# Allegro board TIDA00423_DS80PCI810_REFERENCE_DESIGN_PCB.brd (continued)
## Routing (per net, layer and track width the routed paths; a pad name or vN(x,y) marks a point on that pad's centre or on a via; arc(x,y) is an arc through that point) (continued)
VDD_SEL3_4: length 5
  TOP w0.762: SW7.3 v1(82.39,35.2)
  BOTTOM w0.229: U4.25 v1(120.33,38.77) ; v1(75.52,38.75) 75.51,38.75 75.49,38.77 U3.25
VIN1_2: length 56.1
  TOP w0.229: U2.24 v1(119.88,25.03) ; U1.24 75.8,25.03
  TOP w0.292: 75.8,25.03 76.01,25.03
  TOP w0.508: 98.11,24.79 J3.2 ; C160.2 95.62,24.79 ; 76.01,25.03 77.03,25.03
  TOP w0.762: 77.03,25.03 80.09,25.03 81.27,26.21 91.35,26.21 92.8,24.76 C160.2 ; 95.62,24.79 98.11,24.79
  POWER1 w0.762: v1(107.83,19.19) 105.53,19.19 v1(100.7,24.03)
  BOTTOM w0.381: 100.7,24.88 C21.2
  BOTTOM w0.508: J3.2 98.27,24.95 ; v1(119.88,25.03) 119.56,25.03 119.06,24.53 119.06,24.41
  BOTTOM w0.762: v1(100.7,24.03) 100.7,24.88 ; 119.06,24.41 118.94,24.29 118.94,21.17 118.7,20.94 118.7,20.94 116.56,18.79 116.55,18.79 116.4,18.64 108.39,18.64 v1(107.83,19.19) ; 98.27,24.95 C21.2
VIN3_4: length 125.2
  POWER1 w0.229: 119.37,37.74 119.37,38.87 v1(119.77,39.27) ; 75.79,39.23 75.73,39.23 75.72,39.24 75,39.24 v1(74.97,39.27)
  POWER1 w0.292: 119.37,37.74 119.37,37.33 119.82,36.88 ; 119.85,26.86 119.32,26.33 119.32,22.02 ; 75.79,39.23 76.52,39.23 76.8,38.96
  POWER1 w0.508: 76.8,38.96 77.47,38.29 ; 119.8,21.05 119.32,21.54 119.32,22.02
  POWER1 w0.762: 119.82,36.88 120.27,36.43 120.27,27.29 119.85,26.86 ; 77.47,38.29 78.68,37.07 78.68,17.52 84.95,11.25 111.71,11.25 119.8,19.34 119.8,21.05
  BOTTOM w0.229: U4.24 v1(119.77,39.27) ; U3.24 v1(74.97,39.27) 75.85,39.27
  BOTTOM w0.292: 76.04,39.27 75.85,39.27
  BOTTOM w0.635: 77.53,39.27 76.04,39.27
  BOTTOM w0.762: C22.2 98.45,40.96 J5.2 98.36,38.94 C161.2 98.33,37.84 97.19,36.7 82.09,36.7 79.51,39.27 77.53,39.27
3_3V: length 30.2
  TOP w0.508: 84.39,20.6 85.54,20.6 85.86,20.28 85.86,20.27 v1(85.85,20.27) ; U6.4 v1(82.46,39.52)
  TOP w0.635: J1.B8 52.65,6.97 51.83,7.79 v1(51.8,7.79) ; J2.B8 52.65,58.12 v1(52.38,57.86)
  BOTTOM w0.381: J1.A9 53.65,7.59 v1(53.99,7.93)
  BOTTOM w0.508: v1(54.18,7.18) 54.65,6.71 J1.A10 ; v1(85.85,20.27) 85.41,20.71 C23.2 ; C24.2 83.9,39.52 v1(82.46,39.52)
  BOTTOM w0.635: v1(54.18,7.18) 54.18,7.73 v1(53.99,7.93) ; J2.A9 53.65,57.85 v1(53.94,57.56) 54.39,57.56 v1(54.65,57.82) J2.A10 ; R6.1 v1(87.33,43.71) ; R3.1 v1(87.48,24.79)
3_3VAUX: length 59.2
  TOP w0.292: J2.B10 54.65,58.7 55.31,58.04 55.31,56.92 52.46,54.07 52.46,10.99 54.85,8.61 54.85,6.46 54.65,6.26 J1.B10
A_D1: length 100.4
  TOP w0.229: U1.27 v1(75.53,26.53)
  TOP w0.292: R7.2 v1(131.12,30.03) ; SW9.8 v1(138.39,19.83)
  POWER1 w0.292: v1(138.39,19.83) 138.39,26.29 136.84,27.84 134.43,27.84 132.24,30.03 v1(131.12,30.03) 129.61,30.03 126.56,26.97 126.56,21.36 113.68,8.48 84.25,8.48 76.24,16.48 76.24,25.82 v1(75.53,26.53)
A_D2: length 32.3
  TOP w0.229: U2.27 120.89,26.53
  TOP w0.292: 120.89,26.53 127.06,26.53 128.24,27.71 130.75,27.71 132.86,29.82 132.86,30.76 ; 132.86,30.76 R8.2 ; 132.86,30.76 134.05,30.76 134.85,29.96 134.85,22.66 135.79,21.72 138.09,21.72 138.75,22.37 SW9.7
A_D3: length 121.5
  TOP w0.292: SW9.6 139.59,24.91 137.8,26.71 137.8,37.35 137.02,38.13 135.03,38.13 134.05,39.11 R9.2 v1(133.28,39.89)
  POWER1 w0.292: v1(133.28,39.89) 131.95,39.89 125.49,33.42 125.49,21.9 113.13,9.54 84.58,9.54 77.31,16.82 77.31,27.38 75.52,29.16 v1(75.52,37.75)
  BOTTOM w0.229: U3.27 75.5,37.77 v1(75.52,37.75)
A_D4: length 35
  TOP w0.292: v1(137.69,40.01) R10.2 136.97,39.14 138.32,37.79 138.32,30.55 140.29,28.58 SW9.5
  BOTTOM w0.229: U4.27 120.87,37.77
  BOTTOM w0.292: 120.87,37.77 126.33,37.77 129.07,40.51 137.19,40.51 v1(137.69,40.01)
DEMA0_SDA_DS: length 174.8
  TOP w0.229: 62.14,25.02 62.96,25.02 v1(62.98,25.03) U1.49 ; U2.49 v1(107.78,25.03)
  TOP w0.292: 49.85,50.86 49.85,50.26 48.32,48.74 41.21,48.74 39.81,50.14 39.81,50.26 ; 62.14,25.02 60.53,25.02 54.75,30.8 v1(54.75,32.08) ; 39.81,50.26 38.29,48.74 33.08,48.74 32.28,49.54 SW17.4 v1(32.28,52.42) ; 39.81,50.26 SW15.4
  POWER1 w0.229: v1(107.78,25.03) 107.85,25.1 108.21,25.1 109.52,26.41 109.52,26.87 ; 62.14,24.97 62.91,24.97 v1(62.98,25.03) ; 61.51,38.2 61.69,38.38 65.08,38.38 66.36,39.66 66.36,41.79 66.42,41.86 66.42,42.06 ; 106.48,38.27 106.5,38.29 108.61,38.29 109.16,37.74
  POWER1 w0.292: 109.16,37.74 109.52,37.38 109.52,26.87 ; 106.48,38.27 106.14,38.27 103.35,41.05 103.35,44.59 98.24,49.71 73.47,49.71 66.42,42.66 66.42,42.06 ; v1(54.75,32.08) 55.28,32.61 55.28,34.41 50.03,39.67 34.84,39.67 29.2,45.31 29.2,52.8 29.83,53.44 31.56,53.44 32.32,52.68 32.32,52.46 v1(32.28,52.42) ; 61.51,38.2 59.08,35.77 59.08,26.94 61.06,24.97 62.14,24.97
DEMA0_SDA_US: length 95.8
  TOP w0.292: SW16.4 36,38.45 37.02,39.47 38.54,39.47 39.81,40.74 SW15.1 39.81,43.76 39.89,43.84 v1(39.89,43.91)
  POWER1 w0.229: 65.43,42.06 65.43,40.9 63.87,39.34 61.77,39.34 v1(61.74,39.37) ; 106.48,39.33 106.53,39.28 v1(108.14,39.28)
  POWER1 w0.292: 65.43,42.06 65.43,43.65 72.48,50.7 98.69,50.7 104.53,44.85 104.53,41.27 106.48,39.33
  BOTTOM w0.229: v1(108.14,39.28) 108.14,39.28 108.15,39.27 U4.49 ; v1(61.74,39.37) 61.84,39.27 U3.49
  BOTTOM w0.292: v1(61.74,39.37) 44.42,39.37 v1(39.89,43.91)
DEMA1_SCL_DS: length 173.9
  TOP w0.229: U1.50 62.72,24.53 v1(62.49,24.31) 62.14,24.31 ; U2.50 v1(107.33,24.53)
  TOP w0.292: 62.14,24.31 60.54,24.31 54.22,30.63 54.22,32.71 v1(54.72,33.22) ; SW4.2 47.26,50.91 SW15.3 42.35,51.53 40.96,52.93 35.33,52.93 v1(34.82,52.42) SW17.3
  POWER1 w0.229: 110.01,26.87 110.01,26.3 108.25,24.53 v1(107.33,24.53) ; 109.86,37.74 108.83,38.77 106.62,38.77 ; 62.36,38.85 64.03,38.85 65.93,40.74 65.93,42.06
  POWER1 w0.292: v1(62.49,24.31) 61.02,24.31 58.59,26.74 58.59,36.24 61.19,38.85 62.36,38.85 ; 110.01,26.87 110.01,37.59 109.86,37.74 ; 65.93,42.06 65.93,43.08 73.05,50.2 98.44,50.2 103.9,44.75 103.9,41.21 106.33,38.77 106.62,38.77 ; v1(54.72,33.22) 49.19,38.76 34.4,38.76 28.68,44.49 28.68,53.04 29.59,53.95 33.31,53.95 34.82,52.44 v1(34.82,52.42)
DEMA1_SCL_US: length 92.7
  TOP w0.292: v1(42.35,43.91) SW15.2 42.35,40.36 41.08,39.09 39.31,39.09 38.54,38.33 SW16.3
  POWER1 w0.229: v1(62.47,39.88) 62.57,39.77 63.67,39.77 64.94,41.04 64.94,42.06 ; 106.48,40.19 106.9,39.77 v1(107.33,39.77)
  POWER1 w0.292: 106.48,40.19 105.12,41.55 105.12,45.08 98.95,51.25 72.23,51.25 64.94,43.96 64.94,42.06
  BOTTOM w0.229: 62.15,39.9 62.18,39.88 v1(62.47,39.88) 62.57,39.77 U3.50 ; U4.50 v1(107.33,39.77)
  BOTTOM w0.292: 62.15,39.9 46.36,39.9 v1(42.35,43.91)
DEMB0_AD1_DS: length 184.9
  TOP w0.229: U1.53 v1(62.98,23.03) ; U2.53 v1(107.78,23.03)
  TOP w0.292: SW17.1 v1(32.28,44) ; 17.84,26.55 SW5.11 22.92,26.55 v1(22.92,28.29)
  POWER1 w0.229: 62.14,23.04 62.97,23.04 v1(62.98,23.03) 62.98,23.03 63.43,22.58 63.43,22.22 ; 106.48,41.83 106.95,41.36 108.36,41.36 109.61,40.11 109.61,39.39 111.02,37.98 111.02,37.74 ; 61.07,40.99 62.68,40.99 63.75,42.06 ; 110.3,23.04 107.79,23.04 v1(107.78,23.03)
  POWER1 w0.292: 63.43,22.22 63.43,21.78 62.68,21.03 54.95,21.03 48.35,27.63 23.58,27.63 v1(22.92,28.29) ; 63.75,42.06 63.87,42.18 63.87,44.57 71.58,52.28 99.48,52.28 106.31,45.45 106.31,42 106.48,41.83 ; 111.02,37.74 111.02,23.76 110.3,23.04 ; 62.14,23.04 60.59,23.04 57.48,26.14 57.48,37.5 60.97,40.99 61.07,40.99
  BOTTOM w0.292: v1(22.92,28.29) 23.61,28.98 28.87,28.98 33.31,33.42 33.31,42.97 v1(32.28,44)
DEMB0_AD1_US: length 123.6
  TOP w0.292: SW3.12 SW3.10 22.67,37.64 23.51,36.8 30.16,36.8 36,30.96 v1(36,30.25) SW16.1
  POWER1 w0.229: v1(62.31,42.14) 62.18,42.01 60.9,42.01
  POWER1 w0.292: v1(36,30.25) 36.82,29.44 54.47,29.44 56.34,31.3 56.34,38.03 60.31,42.01 60.9,42.01 ; v1(62.31,42.14) 62.32,42.14 62.8,42.62 62.8,45.49 70.7,53.39 99.99,53.39 107.65,45.72 v1(107.65,42.34)
  BOTTOM w0.229: v1(62.31,42.14) 63.17,41.27 U3.53 ; v1(107.65,42.34) 107.65,41.97 108.34,41.27 U4.53
DEMB1_AD0_DS: length 186.4
  TOP w0.229: U2.54 v1(107.33,22.53) ; U1.54 v1(62.52,22.53)
  TOP w0.292: SW17.2 v1(34.82,44) ; SW5.7 SW5.9 v1(25.46,28.29)
  POWER1 w0.229: 62.14,22.54 62.51,22.54 v1(62.52,22.53) 62.8,22.53 62.94,22.39 62.94,22.22 ; 60.97,41.49 62.47,41.49 63.05,42.06 ; v1(107.33,22.53) 107.33,22.54 111.83,22.54 ; 107.07,42.07 107.35,41.8 108.93,41.8
  POWER1 w0.292: 111.83,22.54 112.43,23.14 112.43,39.95 111.87,40.51 110.42,40.51 109.13,41.8 108.93,41.8 ; 107.07,42.07 106.81,42.33 106.81,45.66 99.69,52.78 71.13,52.78 63.36,45.01 63.36,42.38 63.05,42.06 ; 62.94,22.22 62.94,21.98 62.7,21.74 55.59,21.74 49.04,28.29 v1(25.46,28.29) ; 62.14,22.54 60.38,22.54 56.99,25.94 56.99,37.87 60.6,41.49 60.97,41.49
  BOTTOM w0.292: v1(25.46,28.29) 29.63,28.29 34.25,32.92 34.25,43.43 v1(34.82,44)
DEMB1_AD0_US: length 115
  TOP w0.292: SW16.2 v1(38.54,30.22) 37.88,30.22 30.29,37.82 SW3.7 SW3.8 25.21,39.37
  POWER1 w0.229: v1(62.24,42.95) 60.9,42.95
  POWER1 w0.292: 60.9,42.95 60.41,42.95 55.84,38.38 55.84,32.1 53.96,30.22 v1(38.54,30.22) ; v1(108.37,42.59) 108.37,45.82 100.27,53.92 70.37,53.92 62.24,45.79 v1(62.24,42.95)
  BOTTOM w0.229: v1(108.37,42.59) 108.37,41.98 108.58,41.77 U4.54 ; v1(62.24,42.95) 62.55,42.95 63.73,41.77 U3.54
ENSMB: length 174.3
  TOP w0.229: U2.48 v1(107.33,25.53) ; U1.48 62.54,25.53 v1(62.52,25.51)
  TOP w0.292: SW2.4 SW2.5 SW2.6 v1(25.46,41.49)
  POWER1 w0.229: v1(107.33,25.53) 108.03,25.53 109.02,26.53 109.02,26.87 ; 63.53,25.53 62.77,25.53 62.76,25.51 v1(62.52,25.51) ; 108.42,37.74 108.37,37.79 v1(107.3,37.79)
  POWER1 w0.254: 67.65,42.06 67.65,39.55 67.3,39.19 66.64,39.19 65.37,37.93 62.58,37.93 v1(62.32,37.67)
  POWER1 w0.292: 63.53,25.53 64.2,24.86 64.2,21.66 62.85,20.32 54.27,20.32 47.74,26.85 22.72,26.85 19.01,30.55 19.01,38.66 21.85,41.49 v1(25.46,41.49) ; v1(62.52,25.51) 61.22,25.51 59.58,27.15 59.58,35.53 61.71,37.67 v1(62.32,37.67) ; 67.65,42.06 67.65,43 73.86,49.21 98.03,49.21 102.86,44.39 102.86,40.85 105.93,37.77 107.28,37.77 v1(107.3,37.79) ; 108.42,37.74 109.02,37.14 109.02,26.87
  BOTTOM w0.229: U3.48 63.22,38.77 62.32,37.87 v1(62.32,37.67) ; U4.48 108.03,38.77 107.3,38.05 v1(107.3,37.79)
EQA0_DS: length 232.4
  TOP w0.229: U2.46 v1(107.33,26.53) ; U2.20 v1(119.88,23.03) ; U1.20 75.15,23.03 v1(75.3,22.88) ; U1.46 v1(62.52,26.53)
  TOP w0.292: SW1.12 SW1.11 SW1.10 v1(26.61,56.77)
  POWER1 w0.229: 66.26,22.22 66.26,25.08 64.63,26.71 62.7,26.71 v1(62.52,26.53) 62.25,26.53 62.14,26.64 ; v1(107.33,26.53) 107.33,26.87 ; v1(75.3,22.88) 75.5,22.68 75.5,22.22 ; 69.02,22.22 69.02,26.86 ; 73.61,40.97 73.92,41.28 75.96,41.28
  POWER1 w0.292: 66.26,22.22 66.26,21.64 63.36,18.74 53.61,18.74 47.1,25.24 21.48,25.24 16.88,29.84 16.88,50.78 23.39,57.3 26.07,57.3 v1(26.61,56.77) ; 62.14,26.64 61.82,26.96 61.82,28.68 62.57,29.44 66.64,29.44 69.02,27.05 69.02,26.86 ; 73.61,40.97 72.9,40.27 72.9,24.67 74.53,23.04 75.14,23.04 v1(75.3,22.88) ; 107.33,26.87 107.33,33.12 100.8,39.65 100.8,43.52 99.19,45.13 80.17,45.13 76.33,41.28 75.96,41.28 ; 69.02,22.22 69.02,21.94 70.55,20.42 74.36,20.42 75.5,21.56 75.5,22.22
  BOTTOM w0.229: 106.94,26.53 v1(107.33,26.53) ; v1(119.88,23.03) 119.88,23.03 120.54,23.03 120.89,22.67 120.89,22.24
  BOTTOM w0.292: 106.94,26.53 106.76,26.53 106.08,25.85 106.08,18.49 107.86,16.71 116.78,16.71 120.89,20.83 120.89,22.24
EQA0_US: length 134.6
  TOP w0.229: v1(119.77,41.27) 118.94,40.43 118.94,39.29 117.41,37.76 117.41,37.74
  TOP w0.292: SW11.12 SW11.11 SW11.10 v1(151.3,23.85) ; 117.41,37.74 115.13,35.46 111.72,35.46 110.35,36.83 v1(108.5,36.83)
  POWER1 w0.229: v1(63.41,36.95) 63.46,36.9 64.33,36.9 ; 71.26,42.06 70.45,41.25 70.45,38.05 69.83,37.43 ; v1(119.77,41.27) 121.4,41.27
  POWER1 w0.292: v1(151.3,23.85) 147.75,23.85 145.61,25.99 145.61,30.76 147.72,32.87 147.72,37.33 143.78,41.27 121.4,41.27 ; 71.26,42.06 71.49,42.29 74.99,42.29 75.22,42.51 75.22,42.51 v1(75.32,42.61) 75.32,42.62 80.91,48.21 97.64,48.21 101.8,44.04 101.8,40.5 105.55,36.76 108.43,36.76 v1(108.5,36.83) ; 69.83,37.43 69.3,36.9 64.33,36.9
  BOTTOM w0.229: v1(75.32,42.61) 75.32,42.11 74.49,41.27 U3.20 ; U3.46 63.8,37.77 63.44,37.41 63.44,36.98 v1(63.41,36.95) ; v1(108.5,36.83) 108.39,36.93 108.39,37.49 108.68,37.77 U4.46 ; U4.20 v1(119.77,41.27)
EQA1_DS: length 221.5
  TOP w0.229: U2.47 v1(107.78,26.03) ; U1.19 74.43,22.53 v1(74.61,22.35) ; U1.47 v1(62.98,26.03) ; U2.19 v1(120.33,22.53)
  TOP w0.292: SW1.7 SW1.8 SW1.9 v1(24.07,56.77)
  POWER1 w0.229: 72.67,40.83 71.86,40.02 71.86,37.98 71.85,37.97 ; 73.61,41.76 73.62,41.78 75.96,41.78 ; v1(74.61,22.35) 74.49,22.22 ; 108.01,26.87 108.01,26.26 v1(107.78,26.03) ; 70.57,26.86 70.57,23.09 71.44,22.22 ; 64.78,22.22 64.78,25.6 64.35,26.03 v1(62.98,26.03) 62.14,26.03
  POWER1 w0.254: v1(74.61,22.35) 74.4,22.57 73.53,22.57 71.87,24.23 71.87,26.14
  POWER1 w0.292: 71.85,37.97 71.85,37.96 71.87,37.94 71.87,26.14 ; 71.44,22.22 71.84,21.82 74.08,21.82 74.49,22.22 ; 64.78,22.22 64.78,21.21 63.11,19.53 54.09,19.53 47.56,26.06 22.09,26.06 18.17,29.97 18.17,49.55 22.03,53.41 22.03,54.73 v1(24.07,56.77) ; 70.57,26.86 70.57,27.81 68.06,30.32 62.29,30.32 61.15,29.18 61.15,26.79 61.91,26.03 62.14,26.03 ; 108.01,26.87 108.01,33.4 101.31,40.1 101.31,43.73 99.28,45.76 79.93,45.76 75.96,41.78 75.96,41.78 ; 73.61,41.76 72.67,40.83
  BOTTOM w0.229: v1(107.78,26.03) 107.08,26.03 106.94,25.89 ; v1(120.33,22.53) 120.04,22.24
  BOTTOM w0.292: 120.04,22.24 120,22.2 120,20.67 116.73,17.4 107.99,17.4 106.62,18.77 106.62,25.57 106.94,25.89
EQA1_US: length 131.3
  TOP w0.229: 106.83,42.07 106.83,39.33 107.83,38.33 107.83,37.3 v1(107.81,37.28) ; 120.03,42.07 v1(120.33,41.77)
  TOP w0.292: 106.83,42.07 106.83,42.35 108.62,44.14 117.96,44.14 120.03,42.07 ; v1(151.35,31.47) SW11.7 SW11.8 SW11.9
  POWER1 w0.229: v1(62.73,37.16) 63.05,37.48 68.26,37.48 69.13,38.35 69.13,42.06
  POWER1 w0.292: v1(151.35,31.47) 151.35,34.4 143.98,41.77 136.88,41.77 136.88,41.77 v1(120.33,41.77) ; 69.13,42.06 69.13,42.42 70.63,43.91 73.5,43.91 v1(74.54,42.87) 74.54,42.95 80.3,48.71 97.83,48.71 102.3,44.24 102.3,40.71 105.74,37.27 107.79,37.27 v1(107.81,37.28)
  BOTTOM w0.229: v1(107.81,37.28) 107.81,37.67 108.42,38.27 U4.47 ; U4.19 v1(120.33,41.77) ; v1(62.73,37.16) 62.73,37.36 63.64,38.27 U3.47 ; v1(74.54,42.87) 74.54,42.03 74.28,41.77 U3.19
JTAG1: length 58.1
  TOP w0.292: J2.B9 53.65,58.44 53.32,58.12 53.32,56.08 51.96,54.71 51.96,10.36 53.32,8.99 53.32,6.26 53.65,5.94 J1.B9
JTAG2: length 70.4
  BOTTOM w0.292: J1.A5 49.65,6.07 48.73,6.99 48.73,13.44 37.02,25.15 37.02,32.7 36.02,33.7 36.02,48.24 44.12,56.35 48.13,56.35 49.65,57.86 J2.A5
JTAG3: length 70.7
  BOTTOM w0.292: J2.A6 50.65,58.17 50.15,57.67 50.15,57.66 48.27,55.78 44.32,55.78 36.51,47.98 36.51,33.91 37.81,32.61 37.81,25.67 49.57,13.91 49.57,7.18 50.65,6.1 J1.A6
JTAG4: length 71.7
  BOTTOM w0.292: J1.A7 51.65,5.94 50.62,6.96 50.62,13.67 39.21,25.09 39.21,32.28 37.07,34.41 37.07,47.84 44.43,55.19 49.39,55.19 51.58,57.38 51.58,60.18 J2.A7
JTAG5: length 72.8
  BOTTOM w0.292: J2.A8 52.65,58.62 52.98,58.28 52.98,57.28 50.37,54.67 44.6,54.67 37.61,47.67 37.61,34.77 39.76,32.61 39.76,25.98 52.65,13.1 J1.A8
PERN0: length 3.6
  BOTTOM w0.203: U3.44 65.23,37.08 65.23,35.54 64.62,34.93 64.62,33.93 C64.1
PERN0_C: length 3.6
  BOTTOM w0.203: U3.2 65.27,43.15 65.25,43.17 65.25,44.04 64.62,44.68 64.62,45.63 C128.1
PERN1: length 3.5
  BOTTOM w0.203: C66.1 65.96,33.92 65.96,34.81 66.22,35.08 66.22,37.07 U3.42
PERN1_C: length 3.5
  BOTTOM w0.203: U3.4 66.27,43.15 66.25,43.17 66.25,44.43 65.92,44.76 65.92,45.62 C130.1
PERN2: length 3.5
  BOTTOM w0.203: U3.39 67.77,35.73 67.29,35.25 67.29,33.9 C68.1
PERN2_C: length 3.4
  BOTTOM w0.203: C132.1 67.27,45.65 U3.6
PERN3: length 3.4
  BOTTOM w0.203: U3.37 68.77,37.12 68.77,35.38 68.57,35.17 68.57,33.94 C70.1
PERN3_C: length 3.5
  BOTTOM w0.203: C134.1 68.6,45.65 68.6,44.69 68.25,44.35 68.25,42.45 U3.8
PERN4: length 3.5
  BOTTOM w0.203: U3.34 70.23,37.08 70.23,35.19 69.88,34.83 69.88,33.96 C72.1
PERN4_C: length 3.4
  BOTTOM w0.203: U3.11 69.75,42.45 69.75,44.69 69.9,44.84 69.9,45.63 C136.1
PERN5: length 3.3
  BOTTOM w0.203: U3.32 71.27,36.4 71.25,36.37 71.25,33.9 C74.1
PERN5_C: length 3.6
  BOTTOM w0.203: C138.1 71.23,45.64 71.23,43.99 70.77,43.53 70.77,42.43 U3.13
PERN6: length 3.5
  BOTTOM w0.203: C76.1 72.55,33.93 72.55,35.03 72.25,35.33 72.25,36.37 72.27,36.4 U3.30
PERN6_C: length 3.5
  BOTTOM w0.203: C140.1 72.57,45.66 72.57,44.59 72.27,44.29 72.27,42.42 U3.16
PERN7: length 3.6
  BOTTOM w0.203: U3.28 73.23,37.08 73.23,35.87 73.88,35.23 73.88,33.92 C78.1
PERN7_C: length 3.6
  BOTTOM w0.203: C142.1 73.85,45.62 73.85,44.55 73.25,43.95 73.25,43.17 73.27,43.15 U3.18
PERN8: length 3.6
  BOTTOM w0.203: U4.44 110.08,35.58 109.43,34.93 109.43,33.93 C80.1
PERN8_C: length 3.6
  BOTTOM w0.203: U4.2 110.04,42.47 110.04,42.61 110.02,42.63 110.02,44.09 109.42,44.68 109.42,45.63 C144.1
PERN9: length 3.5
  BOTTOM w0.203: U4.42 111.08,35.13 110.76,34.81 110.76,33.92 C82.1
PERN9_C: length 3.5
  BOTTOM w0.203: U4.4 111.04,42.47 111.04,44.45 110.73,44.76 110.73,45.62 C146.1
PERN10: length 3.5
  BOTTOM w0.203: U4.39 112.58,35.73 112.1,35.25 112.1,33.9 C84.1
PERN10_C: length 3.4
  BOTTOM w0.203: U4.6 112.08,45.65 C148.1
PERN11: length 3.4
  BOTTOM w0.203: C86.1 113.5,33.88 113.38,34 113.38,35.3 113.54,35.46 113.54,37.08 U4.37
PERN11_C: length 3.5
  BOTTOM w0.203: C150.1 113.4,45.65 113.4,44.69 113.04,44.33 113.04,42.46 U4.8
PERN12: length 3.5
  BOTTOM w0.203: C88.1 114.72,33.92 114.72,34.87 115.08,35.23 U4.34
PERN12_C: length 3.4
  BOTTOM w0.203: U4.11 114.58,44.71 114.71,44.84 114.71,45.63 C152.1
PERN13: length 3.3
  BOTTOM w0.203: C90.1 116.06,33.91 116.06,37.1 U4.32
PERN13_C: length 3.6
  BOTTOM w0.203: U4.13 115.57,42.44 115.57,43.87 116.04,44.34 116.04,45.64 C154.1
PERN14: length 3.5
  BOTTOM w0.203: C92.1 117.35,33.93 117.35,35.03 117.06,35.33 117.06,37.1 U4.30
PERN14_C: length 3.5
  BOTTOM w0.203: C156.1 117.38,45.66 117.38,44.59 117.08,44.29 117.08,42.42 U4.16
PERN15: length 3.6
  BOTTOM w0.203: U4.28 118.04,37.08 118.04,35.87 118.68,35.23 118.68,33.92 C94.1
PERN15_C: length 3.6
  BOTTOM w0.203: C158.1 118.66,45.62 118.66,44.55 118.06,43.95 118.06,42.44 U4.18
PERP0: length 3.6
  BOTTOM w0.203: C63.1 64.16,33.91 64.16,35.12 64.77,35.73 U3.45
PERP0_C: length 3.6
  BOTTOM w0.203: U3.1 64.77,43.15 64.8,43.17 64.8,43.85 64.16,44.49 64.16,45.66 C127.1
PERP1: length 3.5
  BOTTOM w0.203: C65.1 65.5,33.93 65.5,35 65.77,35.27 65.77,37.12 U3.43
PERP1_C: length 3.5
  BOTTOM w0.203: U3.3 65.77,43.15 65.8,43.17 65.8,44.24 65.46,44.57 65.46,45.68 C129.1
PERP2: length 3.6
  BOTTOM w0.203: U3.40 67.32,37.08 67.32,35.91 66.84,35.43 66.84,33.95 C67.1
PERP2_C: length 3.4
  BOTTOM w0.203: U3.5 66.77,43.15 66.82,43.19 66.82,45.64 C131.1
PERP3: length 3.4
  BOTTOM w0.203: C69.1 68.03,33.87 68.11,33.95 68.11,35.36 68.32,35.56 68.32,37.08 U3.38
PERP3_C: length 3.5
  BOTTOM w0.203: U3.7 67.8,42.44 67.8,44.54 68.14,44.88 68.14,45.64 C133.1
PERP4: length 3.5
  BOTTOM w0.203: U3.35 69.77,37.05 69.78,37.04 69.78,35.38 69.42,35.02 69.42,33.89 C71.1
PERP4_C: length 3.4
  BOTTOM w0.203: C135.1 69.45,45.66 69.45,45.03 69.29,44.87 69.29,42.44 U3.10
PERP5: length 3.4
  BOTTOM w0.203: U3.33 70.77,36.4 70.8,36.37 70.8,33.94 C73.1
PERP5_C: length 3.6
  BOTTOM w0.203: U3.12 70.31,42.46 70.31,43.72 70.77,44.18 70.77,45.65 C137.1
PERP6: length 3.5
  BOTTOM w0.203: U3.31 71.77,36.4 71.8,36.37 71.8,35.14 72.09,34.85 72.09,33.91 C75.1
PERP6_C: length 3.5
  BOTTOM w0.203: U3.15 71.77,42.56 71.82,42.6 71.82,44.48 72.12,44.78 72.12,45.63 C139.1
PERP7: length 3.6
  BOTTOM w0.203: U3.29 72.78,37.12 72.78,35.68 73.42,35.04 73.42,33.95 73.32,33.85 C77.1
PERP7_C: length 3.6
  BOTTOM w0.203: U3.17 72.77,43.15 72.8,43.17 72.8,44.14 73.4,44.74 73.4,45.67 C141.1
PERP8: length 3.6
  BOTTOM w0.203: C79.1 108.97,33.91 108.97,35.12 109.62,35.77 109.62,37.08 U4.45
PERP8_C: length 3.6
  BOTTOM w0.203: U4.1 109.56,42.45 109.56,43.9 108.97,44.49 108.97,45.66 C143.1
PERP9: length 3.5
  BOTTOM w0.203: U4.43 110.62,37.08 110.62,35.32 110.3,35 110.3,33.93 C81.1
PERP9_C: length 3.5
  BOTTOM w0.203: U4.3 110.58,44.26 110.27,44.57 110.27,45.68 C145.1
PERP10: length 3.6
  BOTTOM w0.203: U4.40 112.12,37.08 112.12,35.91 111.64,35.43 111.64,33.95 C83.1
PERP10_C: length 3.4
  BOTTOM w0.203: U4.5 111.62,42.47 111.62,45.64 C147.1
PERP11: length 3.4
  BOTTOM w0.203: U4.38 113.08,35.65 112.92,35.49 112.92,33.94 112.84,33.86 C85.1
PERP11_C: length 3.5
  BOTTOM w0.203: U4.7 112.59,42.43 112.59,44.52 112.95,44.88 112.95,45.64 C149.1
PERP12: length 3.5
  BOTTOM w0.203: U4.35 114.62,37.08 114.62,35.42 114.26,35.06 114.26,33.92 C87.1
PERP12_C: length 3.4
  BOTTOM w0.203: U4.10 114.12,42.47 114.12,42.61 114.12,44.9 114.25,45.03 114.25,45.66 C151.1
PERP13: length 3.4
  BOTTOM w0.203: C89.1 115.6,33.94 115.6,37.11 U4.33
PERP13_C: length 3.6
  BOTTOM w0.203: C153.1 115.58,45.65 115.58,44.53 115.11,44.06 115.11,42.45 U4.12
PERP14: length 3.5
  BOTTOM w0.203: U4.31 116.6,37.11 116.6,35.14 116.9,34.85 116.9,33.91 C91.1
PERP14_C: length 3.5
  BOTTOM w0.203: C155.1 116.92,45.63 116.92,44.78 116.62,44.48 116.62,42.6 116.58,42.56 U4.15
PERP15: length 3.6
  BOTTOM w0.203: C93.1 118.12,33.85 118.22,33.95 118.22,35.04 117.58,35.68 117.58,37.12 U4.29
PERP15_C: length 3.6
  BOTTOM w0.203: U4.17 117.6,42.44 117.6,44.14 118.2,44.74 118.2,45.67 C157.1
PERST: length 75.4
  BOTTOM w0.292: J1.A11 55.65,6.34 55.3,6.68 55.3,8.41 53.73,9.98 53.73,13 40.37,26.36 40.37,32.84 38.11,35.1 38.11,47.32 44.96,54.16 52.05,54.16 55.65,57.77 J2.A11
PETN0: length 3.6
  TOP w0.203: C32.2 64.66,18.66 64.66,19.73 65.27,20.35 U1.2
PETN0_C: length 3.6
  TOP w0.203: U1.44 65.27,27.19 65.25,27.21 65.25,29.06 64.61,29.7 64.61,30.35 64.66,30.4 64.66,30.41 C96.2
PETN1: length 3.5
  TOP w0.203: C34.2 65.98,18.66 65.98,19.73 66.27,20.03 U1.4
PETN1_C: length 3.5
  TOP w0.203: U1.42 66.27,27.19 66.27,29.41 65.98,29.7 65.98,30.41 C98.2
PETN2: length 3.3
  TOP w0.203: U1.6 67.27,18.68 C36.2
PETN2_C: length 3.5
  TOP w0.203: C100.2 67.3,30.41 67.3,29.56 67.75,29.11 67.75,27.2 U1.39
PETN3: length 3.5
  TOP w0.203: C38.2 68.57,18.71 68.57,19.96 68.27,20.25 U1.8
PETN3_C: length 3.4
  TOP w0.203: U1.37 68.73,27.23 68.73,27.37 68.72,27.39 68.72,29.67 68.61,29.78 68.61,30.4 C102.2
PETN4: length 3.4
  TOP w0.203: U1.11 69.77,21.88 69.77,20.12 69.89,20 69.89,18.71 C40.2
PETN4_C: length 3.5
  TOP w0.203: U1.34 70.27,27.19 70.27,29.54 69.94,29.87 69.94,30.41 C104.2
PETN5: length 3.5
  TOP w0.203: U1.13 70.77,20.51 71.18,20.1 71.18,18.73 C42.2
PETN5_C: length 3.4
  TOP w0.203: C106.2 71.24,30.39 71.24,27.22 U1.32
PETN6: length 3.5
  TOP w0.203: C44.2 72.53,18.71 72.53,19.95 72.27,20.21 U1.16
PETN6_C: length 3.5
  TOP w0.203: U1.30 72.3,27.21 72.3,29.35 72.53,29.58 72.53,29.59 72.57,29.63 72.57,30.4 C108.2
PETN7: length 3.6
  TOP w0.203: C46.2 73.85,18.71 73.85,19.95 73.27,20.52 U1.18
PETN7_C: length 3.6
  TOP w0.203: C110.2 73.88,30.38 73.88,29.46 73.27,28.86 U1.28
PETN8: length 3.6
  TOP w0.203: C48.2 109.46,18.71 109.46,19.73 110.08,20.35 U2.2
PETN8_C: length 3.6
  TOP w0.203: C112.2 109.46,30.41 109.46,30.4 109.41,30.35 109.41,29.7 110.04,29.07 110.04,27.4 110.06,27.38 110.06,27.21 110.08,27.19 U2.44
PETN9: length 3.5
  TOP w0.203: U2.4 111.08,20.03 110.78,19.73 110.78,18.71 C50.2
PETN9_C: length 3.5
  TOP w0.203: C114.2 110.78,30.41 110.78,29.7 111.08,29.41 111.08,27.19 U2.42
PETN10: length 3.4
  TOP w0.203: U2.6 112.08,21.3 112.11,21.27 112.11,18.7 C52.2
PETN10_C: length 3.5
  TOP w0.203: C116.2 112.09,30.4 112.09,29.72 112.56,29.25 112.56,27.2 U2.39
PETN11: length 3.5
  TOP w0.203: C54.2 113.37,18.76 113.37,19.96 113.08,20.25 U2.8
PETN11_C: length 3.4
  TOP w0.203: U2.37 113.58,27.19 113.58,29.61 113.41,29.78 113.41,30.4 C118.2
PETN12: length 3.4
  TOP w0.203: U2.11 114.58,21.88 114.58,20.12 114.69,20 114.69,19.95 114.7,19.95 114.7,18.76 114.69,18.76 C56.2
PETN12_C: length 3.5
  TOP w0.203: C120.2 114.74,30.41 114.74,29.87 115.06,29.56 115.06,27.21 U2.34
PETN13: length 3.6
  TOP w0.203: U2.13 115.56,21.86 115.56,19.95 116.09,19.42 116.09,18.69 C58.2
PETN13_C: length 3.3
  TOP w0.203: U2.32 116.07,27.19 116.07,30.41 C122.2
PETN14: length 3.5
  TOP w0.203: U2.16 117.08,20.21 117.34,19.95 117.34,18.76 C60.2
PETN14_C: length 3.5
  TOP w0.203: C124.2 117.37,30.4 117.37,29.63 117.34,29.59 117.34,29.58 117.06,29.3 117.06,27.2 U2.30
PETN15: length 3.6
  TOP w0.203: C62.2 118.66,18.76 118.66,19.95 118.08,20.52 U2.18
PETN15_C: length 3.6
  TOP w0.203: C126.2 118.68,30.38 118.68,29.46 118.05,28.83 118.05,27.21 U2.28
PETP0: length 3.6
  TOP w0.203: C31.2 64.2,18.71 64.2,19.98 64.78,20.56 64.78,21.88 U1.1
PETP0_C: length 3.6
  TOP w0.203: U1.45 64.79,27.2 64.79,28.87 64.15,29.51 64.15,30.41 C95.2
PETP1: length 3.5
  TOP w0.203: U1.3 65.78,21.88 65.78,20.18 65.52,19.92 65.52,18.71 C33.2
PETP1_C: length 3.5
  TOP w0.203: U1.43 65.77,29.26 65.52,29.51 65.52,30.36 C97.2
PETP2: length 3.4
  TOP w0.203: U1.5 66.82,21.84 66.82,18.69 C35.2
PETP2_C: length 3.6
  TOP w0.203: U1.40 67.3,27.2 67.3,28.92 66.84,29.37 66.84,30.36 C99.2
PETP3: length 3.5
  TOP w0.203: C37.2 68.11,18.66 68.11,19.72 67.78,20.05 67.78,21.88 U1.7
PETP3_C: length 3.4
  TOP w0.203: C101.2 68.11,30.41 68.11,29.63 68.26,29.48 68.26,27.2 U1.38
PETP4: length 3.4
  TOP w0.203: C39.2 69.43,18.66 69.43,19.76 69.27,19.91 U1.10
PETP4_C: length 3.5
  TOP w0.203: U1.35 69.81,27.22 69.81,29.35 69.48,29.68 69.48,30.36 C103.2
PETP5: length 3.5
  TOP w0.203: C41.2 70.73,18.63 70.73,19.86 70.28,20.31 70.28,21.88 U1.12
PETP5_C: length 3.3
  TOP w0.203: C105.2 70.78,30.38 70.78,27.19 U1.33
PETP6: length 3.5
  TOP w0.203: U1.15 71.78,21.88 71.78,20 72.07,19.71 72.07,18.66 C43.2
PETP6_C: length 3.5
  TOP w0.203: U1.31 71.82,27.23 71.82,27.37 71.84,27.4 71.84,29.54 72.07,29.77 72.07,30.41 C107.2
PETP7: length 3.6
  TOP w0.203: C45.2 73.39,18.66 73.39,19.76 72.78,20.37 72.78,21.88 U1.17
PETP7_C: length 3.6
  TOP w0.203: U1.29 72.82,27.23 72.82,29.05 73.42,29.65 73.42,30.38 C109.2
PETP8: length 3.6
  TOP w0.203: U2.1 109.59,21.88 109.59,20.56 109,19.97 109,18.65 C47.2
PETP8_C: length 3.6
  TOP w0.203: C111.2 108.95,30.41 108.95,29.51 109.59,28.88 109.59,27.19 U2.45
PETP9: length 3.4
  TOP w0.203: U2.3 110.59,21.88 110.59,20.18 110.33,19.92 110.33,18.66 C49.2
PETP9_C: length 3.5
  TOP w0.203: C113.2 110.33,30.36 110.33,29.51 110.58,29.26 U2.43
PETP10: length 3.4
  TOP w0.203: C51.2 111.66,18.67 111.66,21.08 111.58,21.16 U2.5
PETP10_C: length 3.6
  TOP w0.203: C115.2 111.63,30.37 111.63,29.53 112.1,29.06 112.1,27.2 U2.40
PETP11: length 3.5
  TOP w0.203: U2.7 112.59,21.88 112.59,20.05 112.92,19.72 112.92,18.61 C53.2
PETP11_C: length 3.4
  TOP w0.203: U2.38 113.12,27.22 113.12,29.42 112.92,29.63 112.92,30.41 C117.2
PETP12: length 3.4
  TOP w0.203: C55.2 114.24,18.61 114.24,18.95 114.24,18.95 114.24,19.76 114.08,19.91 U2.10
PETP12_C: length 3.5
  TOP w0.203: U2.35 114.6,27.2 114.6,29.37 114.29,29.68 114.29,30.36 C119.2
PETP13: length 3.6
  TOP w0.203: C57.2 115.53,18.59 115.63,18.68 115.63,19.23 115.1,19.76 115.1,21.86 U2.12
PETP13_C: length 3.4
  TOP w0.203: C121.2 115.61,30.35 115.61,27.22 U2.33
PETP14: length 3.4
  TOP w0.203: C59.2 116.88,18.61 116.88,19.71 116.59,20 116.59,21.88 U2.15
PETP14_C: length 3.5
  TOP w0.203: C123.2 116.88,30.41 116.88,29.77 116.61,29.49 116.61,27.21 U2.31
PETP15: length 3.6
  TOP w0.203: U2.17 117.59,21.88 117.59,20.37 118.2,19.76 118.2,18.61 C61.2
PETP15_C: length 3.6
  TOP w0.203: C125.2 118.22,30.38 118.22,29.65 117.6,29.02 117.6,27.2 U2.29
PRSNT: length 237.2
  TOP w0.229: U1.52 v1(62.52,23.53) ; U2.52 v1(107.33,23.53)
  TOP w0.292: SW14.8 SW14.7 SW14.6 SW14.5 161.46,54.31 159.78,52.63 152.64,52.63 151.13,51.11 151.13,33.79 150.15,32.82 150.15,28.05 149.55,27.45 SW9.4 v1(146.57,27.45)
  POWER1 w0.229: 110.53,37.74 109.11,39.16 109.11,40.01 108.34,40.77 107.64,40.77 v1(107.38,40.51) ; 64.43,42.06 62.8,40.43 v1(61.79,40.43) 61.43,40.43 ; v1(107.33,23.53) 106.94,23.14
  POWER1 w0.254: 108.48,23.53 108.01,23.53 107.99,23.54 107.57,23.54 107.57,23.53 v1(107.33,23.53)
  POWER1 w0.292: 110.53,37.74 110.53,25.58 108.48,23.53 ; v1(146.57,27.45) 148.98,27.45 152.08,30.55 152.08,35.35 143.7,43.74 117.51,43.74 115.43,41.66 115.43,27.91 114.04,26.52 114.04,23.34 112.71,22.01 107.11,22.01 106.8,22.31 106.8,23.01 106.94,23.14 ; 61.43,40.43 58.03,37.03 58.03,26.3 60.79,23.53 v1(62.52,23.53) ; v1(107.38,40.51) 106.9,40.51 105.7,41.7 105.7,45.36 99.28,51.79 72.02,51.79 64.43,44.2 64.43,42.06
  BOTTOM w0.229: U4.52 107.64,40.77 v1(107.38,40.51) ; v1(61.79,40.43) 62.12,40.77 U3.52
PRSNT1: length 65.8
  BOTTOM w0.292: J1.A1 45.65,7.18 47.05,8.59 47.05,13.85 35.45,25.45 35.45,48.49 45.65,58.7 J2.A1
PRSNT2_1: length 254.2
  TOP w0.292: J1.B17 63.65,6.07 63.39,6.33 63.39,6.94 v1(64.1,7.64) ; J2.B17 63.65,57.7 v1(63.97,57.38) ; SW14.1 v1(154.72,63.22)
  POWER1 w0.292: v1(154.72,63.22) 151.91,60.4 134.56,60.4 131.44,57.28 80.11,57.28 79.12,58.27 76.68,58.27 75.79,57.38 v1(63.97,57.38) 63.89,57.38 63.5,56.98 39.83,56.98 33.69,63.12 20.86,63.12 10.35,52.6 10.35,22.88 15.94,17.29 45.17,17.29 50.89,11.58 60.77,11.58 64.1,8.25 v1(64.1,7.64)
PRSNT2_2: length 257.5
  TOP w0.292: J2.B31 77.65,57.57 v1(77.15,57.07) ; SW14.2 v1(154.72,60.68) ; v1(77.25,7.9) 77.65,7.5 J1.B31
  POWER1 w0.292: v1(77.25,7.9) 70.85,14.3 51.91,14.3 45.61,20.6 18.15,20.6 12.97,25.78 12.97,51.76 21.6,60.39 33.75,60.39 38.67,55.47 75.97,55.47 77.14,56.64 77.14,57.06 v1(77.15,57.07) 79.51,57.07 79.79,56.79 133.1,56.79 135.01,58.7 152.74,58.7 v1(154.72,60.68)
PRSNT2_3: length 131.4
  TOP w0.292: SW14.3 v1(154.72,58.14) ; J2.B48 94.65,56 v1(95.09,55.55) 95.19,55.46 95.19,52.64 100.96,46.86 100.96,34.89 103.9,31.95 103.9,19 99.32,14.42 94.15,14.42 92.86,13.14 92.86,7.72 94.65,5.94 J1.B48
  POWER1 w0.292: v1(95.09,55.55) 126.1,55.55 126.84,56.29 136.29,56.29 137.83,57.83 154.42,57.83 v1(154.72,58.14)
PRSNT2_4: length 121.5
  TOP w0.292: J2.B81 127.65,56.36 128.15,55.86 v1(128.15,55.7) ; SW14.4 v1(154.72,55.6) ; J1.B81 127.65,6.02 v1(128,6.37)
  POWER1 w0.292: v1(154.72,55.6) 154.61,55.71 142.98,55.71 142.97,55.69 142.53,55.69 142.51,55.71 128.16,55.71 v1(128.15,55.7) 128.15,54.36 133.36,49.15 141.8,49.15 153.59,37.35 153.59,24.79 145.51,16.7 130.16,16.7 126.35,12.9 126.35,8.02 v1(128,6.37)
RATE: length 189
  TOP w0.229: U1.21 v1(75.53,23.53) ; U2.21 v1(120.33,23.53)
  TOP w0.292: SW10.9 SW10.8 SW10.7 v1(152.99,51.31)
  POWER1 w0.229: v1(75.53,23.53) 75.52,23.54 74.77,23.54 ; 120.85,40.77 v1(120.33,40.77) 120.32,40.77 119.04,40.77 ; 75.85,40.78 75.62,40.78 75.61,40.77 v1(75.52,40.77) 74.24,40.77 74.23,40.77
  POWER1 w0.292: 73.48,40.01 73.41,39.94 73.41,24.9 74.77,23.54 ; 75.85,40.78 76.03,40.78 76.04,40.79 77.84,40.79 80.69,37.94 80.69,18.78 85.99,13.48 110.81,13.48 117.72,20.4 117.72,39.68 118.81,40.77 119.04,40.77 ; 120.34,23.53 121.61,23.53 123.76,25.68 123.76,38.88 121.87,40.78 120.85,40.78 120.85,40.77
  POWER1 w0.305: v1(120.33,23.53) 120.34,23.53 ; 73.48,40.01 74.23,40.77
  BOTTOM w0.229: U3.21 v1(75.52,40.77) ; U4.21 v1(120.33,40.77)
  BOTTOM w0.292: v1(152.99,51.31) 152.99,53.62 148.43,58.19 142.9,58.19 135.4,50.7 134.23,50.7 124.3,40.77 v1(120.33,40.77)
RD_EN2: length 62.7
  TOP w0.229: U2.26 121.18,26.03
  TOP w0.292: 121.18,26.03 126.71,26.03 128.59,24.15 131.28,24.15 136.31,19.12 137.6,19.12 138.8,17.93 148.3,17.93 148.89,18.52 SW9.1 146.01,19.83 143.45,22.4 143.45,36.22 146.95,39.72 SW8.7
RD_EN3: length 138.7
  TOP w0.292: SW9.2 146.11,22.37 144.46,24.03 144.46,34.64 v1(147,37.18) SW8.6
  POWER1 w0.229: 75.96,38.25 74.99,38.25 v1(74.97,38.27)
  POWER1 w0.292: 75.96,38.25 75.97,38.25 76.44,37.77 76.44,29.18 77.8,27.82 77.8,17.02 84.79,10.04 112.71,10.04 124.96,22.29 124.96,33.8 131.88,40.73 142.75,40.73 146.3,37.18 v1(147,37.18)
  BOTTOM w0.229: U3.26 v1(74.97,38.27)
RD_EN4: length 47.6
  TOP w0.292: SW9.3 146.77,24.91 145.48,26.21 145.48,33.07 v1(147.05,34.64) SW8.5
  BOTTOM w0.229: U4.26 120.86,38.27
  BOTTOM w0.292: 120.86,38.27 120.87,38.28 126.08,38.28 129.07,41.27 140.43,41.27 v1(147.05,34.64)
REFCLKN: length 81.4
  BOTTOM w0.292: J2.A14 60.65,57.26 59.2,55.8 56.48,55.8 53.85,53.17 45.64,53.17 39.26,46.78 39.26,36.07 41.57,33.75 41.57,30.99 61.33,11.22 61.33,6.82 60.65,6.14 J1.A14
REFCLKP: length 81.8
  BOTTOM w0.292: J2.A13 59.65,58.39 59.98,58.06 59.98,57.32 59.17,56.51 55.92,56.51 53.07,53.67 45.3,53.67 38.7,47.06 38.7,35.66 40.98,33.37 40.98,30.02 60.82,10.18 60.82,7.11 59.65,5.94 J1.A13
RES: length 166.8
  TOP w0.229: U2.23 v1(120.33,24.53) ; U1.23 v1(75.53,24.53)
  TOP w0.292: SW6.7 SW6.8 SW6.9 141.97,56.99 v1(142.75,56.22)
  POWER1 w0.229: 75.74,39.77 v1(75.52,39.77) 74.69,39.77 ; 119.16,39.36 119.57,39.77 v1(120.33,39.77)
  POWER1 w0.292: 74.69,39.77 74.4,39.48 74.4,25.66 v1(75.53,24.53) ; v1(120.33,39.77) 120.33,39.77 122.11,38 122.11,25.71 120.93,24.53 v1(120.33,24.53) ; 119.16,39.36 118.71,38.91 118.71,19.99 111.15,12.42 85.61,12.42 79.7,18.33 79.7,37.28 77.22,39.76 75.76,39.76 75.74,39.77
  BOTTOM w0.229: U4.23 v1(120.33,39.77) ; U3.23 v1(75.52,39.77)
  BOTTOM w0.292: v1(120.33,39.77) 120.34,39.76 125.04,39.76 134.58,49.3 135.83,49.3 v1(142.75,56.22)
RSV2: length 177.8
  TOP w0.292: v1(76.39,56.64) 76.39,57.25 76.65,57.51 J2.B30 ; v1(76.97,6.99) 77.04,6.99 77.04,6.95 76.99,6.95 76.97,6.93 76.9,6.93 76.65,6.68 J1.B30
  POWER1 w0.292: v1(76.97,6.99) 76.79,6.99 70.5,13.28 51.68,13.28 46.01,18.95 17.82,18.95 12.13,24.64 12.13,52.89 20.13,60.89 34.29,60.89 39.2,55.98 75.73,55.98 v1(76.39,56.64)
RSVD: length 158.3
  POWER1 w0.292: v1(64.86,56.66) 64.68,56.49 39.39,56.49 34.26,61.62 20.07,61.62 11.19,52.74 11.19,23.31 16.34,18.16 45.61,18.16 51.3,12.47 61.48,12.47 65.21,8.73 v1(65.21,6.88)
  BOTTOM w0.292: J1.A19 65.65,6.44 v1(65.21,6.88) ; J2.A19 65.65,57.45 v1(64.86,56.66)
RSVD1: length 63.8
  TOP w0.292: J2.B12 58.65,58.09 53.48,52.92 53.48,11.88 55.3,10.07 58.78,10.07 59.55,9.29 59.55,8.11 58.65,7.21 J1.B12
RSVD2: length 92.6
  TOP w0.292: J2.B82 128.65,55.95 128.68,55.92 128.68,55.78 v1(129.28,55.18) ; v1(128.03,8.68) 128.65,8.06 J1.B82
  POWER1 w0.292: v1(128.03,8.68) 128.03,13.31 130.77,16.04 146.59,16.04 154.55,24 154.55,37.63 142,50.19 134,50.19 129.28,54.91 v1(129.28,55.18)
RSVD3: length 177.4
  POWER1 w0.292: v1(78.02,56.33) 76.65,54.96 38.48,54.96 33.55,59.9 21.8,59.9 13.75,51.85 13.75,26.31 18.71,21.36 46.04,21.36 51.96,15.44 70.83,15.44 v1(78.6,7.67)
  BOTTOM w0.292: v1(78.6,7.67) 79.14,7.13 79.14,6.05 78.65,5.56 J1.A32 ; J2.A32 78.65,58.44 79.12,57.97 79.12,57.44 v1(78.02,56.33)
RSVD4: length 177.2
  POWER1 w0.292: v1(79.06,8.56) 71.29,16.33 52.34,16.33 46.47,22.2 19.98,22.2 14.57,27.61 14.57,50.91 23.05,59.4 33.13,59.4 38.07,54.45 78.53,54.45 v1(80.19,56.12)
  BOTTOM w0.292: J2.A33 79.65,56.66 v1(80.19,56.12) ; v1(79.06,8.56) 79.65,7.97 J1.A33
RSVD5: length 70.1
  TOP w0.292: v1(96.03,56.15) 96.03,52.73 101.62,47.13 101.62,35.22 104.41,32.43 104.41,18.79 99.53,13.92 94.36,13.92 93.37,12.93 93.37,8.37 94.48,7.26 95.75,7.26 v1(96.05,6.96)
  BOTTOM w0.292: J2.A50 96.65,57.06 96.03,56.44 v1(96.03,56.15) ; J1.A50 96.65,6.36 v1(96.05,6.96)
RXDET: length 197.6
  TOP w0.229: U2.22 v1(119.88,24.03) ; U1.22 v1(75.07,24.03)
  TOP w0.292: SW10.10 SW10.11 SW10.12 v1(152.99,35.85)
  POWER1 w0.229: 75.82,40.27 v1(74.97,40.27) ; 120.92,24.03 v1(119.88,24.03) ; v1(119.77,40.27) 119.78,40.27 120.85,40.27
  POWER1 w0.292: 75.82,40.27 77.41,40.27 80.2,37.49 80.2,18.54 85.76,12.98 111,12.98 118.22,20.19 118.22,39.12 118.22,39.12 118.22,39.24 119.26,40.27 v1(119.77,40.27) ; v1(74.97,40.27) 74.49,40.27 73.9,39.69 73.9,25.2 v1(75.07,24.03) ; 120.92,24.03 121.22,24.03 123,25.81 123,38.25 120.98,40.27 120.85,40.27
  BOTTOM w0.229: U3.22 v1(74.97,40.27) ; 121.63,40.27 v1(119.77,40.27) U4.22
  BOTTOM w0.292: 121.63,40.27 124.65,40.27 124.66,40.27 124.66,40.27 134.33,49.93 135.66,49.93 143.4,57.68 148.23,57.68 152.06,53.86 152.06,36.79 v1(152.99,35.85)
SCL: length 264.9
  TOP w0.292: SW4.3 47.31,40.23 45.78,38.71 44.79,38.71 43.78,37.69 v1(43.75,37.69) 43.75,36.05 SW12.4
  POWER1 w0.292: v1(43.75,37.69) 34.43,37.69 27.97,44.16 27.97,57.36 26.99,58.34 22.7,58.34 15.38,51.03 15.38,28.24 19.72,23.9 45.91,23.9 52.59,17.22 73.93,17.22 83.66,7.48 115.4,7.48 126.98,19.07 142.04,19.07 144.95,21.98 144.95,34.52 143.76,35.71 140.02,35.71 J8.3
  BOTTOM w0.292: J8.3 130.82,31.77 128.07,29.02 128.07,24.19 J9.6 131.71,22.96 131.74,22.93 R55.1
SD_TH: length 119.6
  TOP w0.229: U1.26 v1(75.07,26.03)
  TOP w0.292: SW6.10 SW6.11 SW6.12 140.42,42.52 SW8.1 SW8.2 SW8.3 SW8.4 v1(142.81,34.64)
  POWER1 w0.292: v1(75.07,26.03) 74.99,26.11 74.99,26.86 75.43,27.3 76.17,27.3 76.81,26.65 76.81,16.61 84.38,9.05 113.37,9.05 126,21.68 126,27.63 129.02,30.65 138.82,30.65 v1(142.81,34.64)
SDA: length 219.3
  TOP w0.292: SW12.3 v1(46.16,37.51) 46.42,37.51 49.85,40.94 49.85,42.26
  POWER1 w0.292: J9.5 127.14,23.34 127.14,20.67 114.45,7.98 84.03,7.98 73.98,18.03 52.92,18.03 46.42,24.53 20.71,24.53 16.17,29.08 16.17,50.85 23.15,57.83 26.63,57.83 27.47,56.99 27.47,43.28 33.95,36.8 45.43,36.8 46.14,37.51 v1(46.16,37.51)
  BOTTOM w0.292: J8.4 134.81,29.23 131.96,26.38 R56.1 131.86,25.47 131.84,25.5 J9.5
SMCLK: length 62.8
  TOP w0.292: J1.B5 49.65,12.16 43.62,18.18 SW12.1 43.62,29.56 50.97,36.9 50.97,54.66 49.64,55.98 49.64,58.39 49.65,58.39 J2.B5
SMDAT: length 61.4
  TOP w0.292: J1.B6 50.65,12.94 46.16,17.42 SW12.2 46.16,29.31 51.46,34.6 51.46,54.91 50.33,56.04 50.33,58.14 50.65,58.46 J2.B6
VIH: length 14.2
  BOTTOM w0.508: R35.1 v1(144.18,56.74) ; R44.1 v1(156.73,18.77) ; R53.1 v1(144.31,42.19) ; R41.1 v1(156.35,44.55) ; R32.1 v1(144.18,49.12) ; R38.1 v1(156.6,36.8) ; R47.1 v1(156.6,26.39)
  BOTTOM w0.635: R20.1 v1(17.59,35.66) ; R54.2 v1(134.1,20.39) ; R29.1 v1(25.46,23.21) ; R17.1 v1(25.46,48.84) ; R56.2 v1(134.23,25.47) ; R26.1 v1(17.84,23.21) ; R55.2 v1(134.1,22.93) ; R11.1 v1(31.69,58.87) ; R14.1 v1(24.07,58.87) ; R23.1 v1(25.08,35.66)
  vias: v1(30.32,52.3) v1(30.32,51.28) v1(30.32,50.26) v1(30.34,49.25) v1(31.15,52.27) v1(31.15,51.25) v1(31.15,50.24) v1(31.18,49.22) v1(59.45,53.54) v1(59.45,52.82) v1(60.13,53.54) v1(60.13,52.82) v1(60.87,53.54) v1(60.87,52.82)
WAKE: length 59.2
  TOP w0.292: J1.B11 55.65,8.95 52.97,11.63 52.97,53.57 55.94,56.54 55.94,58.15 55.65,58.44 J2.B11
N14347575: length 5.8
  TOP w0.305: C29.2 93.19,20.36 R1.1 92.27,21.23 92.01,21.49 R2.2 91.51,22.23 91.15,21.87 U5.6
N14347651: length 2.9
  TOP w0.292: 84.39,24.41 v1(82.92,24.41)
  BOTTOM w0.305: C25.1 v1(82.92,24.41)
N14347847: length 3.4
  TOP w0.292: U5.8 v1(91.43,24.41)
  BOTTOM w0.292: R3.2 91.05,24.79 v1(91.43,24.41)
N14379250: length 3.2
  TOP w0.292: U6.1 v1(82.39,43.33)
  BOTTOM w0.292: v1(82.39,43.33) 82.51,43.46 C26.1
N14379574: length 6.1
  TOP w0.305: 91.76,41.69 90.86,40.79 U6.6 ; 91.76,41.69 R5.2 ; 91.76,41.69 R4.1 92.4,39.92 92.75,39.57 93.15,39.57 C30.2
N14379914: length 3
  TOP w0.292: U6.8 v1(90.89,43.33)
  BOTTOM w0.292: R6.2 90.51,43.71 v1(90.89,43.33)
N14519010: length 17.8
  TOP w0.292: SW8.8 v1(147.43,42.26)
  BOTTOM w0.292: SW13.1 142.01,47.69 v1(147.43,42.26) 147.36,42.19 R53.2
N14524358: length 3.4
  BOTTOM w0.292: J9.3 137.68,22.2 138.79,22.2 139.57,22.98 R52.2
N14524360: length 3.5
  BOTTOM w0.292: R51.2 139.68,20.44 138.96,21.16 137.67,21.16 J9.2
N14524362: length 2.5
  BOTTOM w0.292: J9.1 136.89,17.85 R50.2
N14693554: length 2.5
  BOTTOM w0.292: R54.1 131.74,20.39 131.71,20.42 J9.7
N143603151: length 2.9
  TOP w0.292: SW1.4 v1(24.07,62.15)
  BOTTOM w0.292: R14.2 v1(24.07,62.15)
N143603431: length 2.9
  TOP w0.292: SW1.5 v1(21.53,62.15)
  BOTTOM w0.292: R15.2 v1(21.53,62.15)
N143603671: length 2.9
  TOP w0.292: SW1.3 v1(26.61,62.15)
  BOTTOM w0.292: v1(26.61,62.15) 26.48,62.02 R13.2
N143605131: length 2.9
  TOP w0.292: SW1.2 v1(29.15,62.15)
  BOTTOM w0.292: v1(29.15,62.15) 29.02,62.02 R12.2
N143605431: length 2.9
  TOP w0.292: SW1.6 v1(18.99,62.15)
  BOTTOM w0.292: v1(18.99,62.15) 18.86,62.02 R16.2
N143605671: length 2.9
  TOP w0.292: SW1.1 v1(31.69,62.15)
  BOTTOM w0.292: R11.2 v1(31.69,62.15)
N144765660: length 39.5
  TOP w0.203: J2.B45 91.91,59.99 91.91,55.72 80.87,44.69 80.87,35.4 78.71,33.24 74.32,33.24 73.42,32.34 73.42,31.19 C109.1
N144766261: length 28.3
  BOTTOM w0.203: J2.A48 94.43,60.02 94.43,57.56 84.79,47.92 74.9,47.92 73.88,46.9 73.88,46.45 C142.2
N144766561: length 28.2
  BOTTOM w0.203: C153.2 115.58,46.45 115.58,48.96 117,50.37 124.92,50.37 125.52,50.98 125.52,54.13 124.82,54.83 120.22,54.83 118.89,56.15 118.89,60 J2.A72
N144766980: length 40
  TOP w0.203: C99.1 66.82,31.19 66.82,33.6 64.4,36.01 59.86,36.01 58.69,37.18 58.69,45.59 69.94,56.84 69.94,59.96 J2.B23
N144767221: length 27.9
  BOTTOM w0.203: C158.2 118.68,46.45 118.68,47.2 119.07,47.59 129.64,47.59 131.23,49.18 131.23,55.39 129.38,57.24 127.93,57.24 127.36,57.82 127.36,59.96 J2.A81
N144767760: length 40
  TOP w0.203: C123.1 116.87,31.09 116.9,31.12 116.9,32.51 119.08,34.69 125.66,34.69 127.13,36.16 127.13,49.52 120.9,55.76 120.9,60 J2.B74
N144768181: length 28.1
  BOTTOM w0.203: J2.A26 72.37,59.97 72.37,56.67 72.52,56.52 73.76,56.52 74.29,55.99 74.29,54.71 73.68,54.1 64.2,54.1 63.84,53.74 63.84,51.33 64.41,50.76 66.55,50.76 67.27,50.04 67.27,46.45 C132.2
N144768421: length 28.5
  BOTTOM w0.203: C130.2 65.95,46.45 65.95,48.59 65.23,49.3 58.94,49.3 58.55,49.7 58.55,50.72 58.91,51.08 61.72,51.08 62.62,51.98 62.62,54.49 63.61,55.48 66.93,55.48 68.41,56.96 68.41,60.01 J2.A22
N144768781: length 28.5
  BOTTOM w0.203: C147.2 111.62,46.45 111.62,48.72 110.32,50.01 102.13,50.01 100.41,51.73 100.41,53.99 102.04,55.62 105.98,55.62 106.92,56.57 106.92,59.97 J2.A60
N144769021: length 27.9
  BOTTOM w0.203: C143.2 109,46.46 109,47.36 108.63,47.72 97.13,47.72 95.37,49.48 95.37,53.76 98.92,57.31 98.92,59.98 J2.A52
N144769680: length 39.7
  TOP w0.203: C95.1 64.17,31.19 64.17,32.15 63.08,33.25 57.07,33.25 54.24,36.08 54.24,50.4 60.91,57.07 60.91,59.99 J2.B14
N144769921: length 28.3
  BOTTOM w0.203: J2.A73 119.35,59.95 119.35,56.34 120.41,55.28 125.01,55.28 125.98,54.32 125.98,50.79 125.11,49.91 117.19,49.91 116.04,48.77 116.04,46.45 C154.2
N144770280: length 39.9
  TOP w0.203: J2.B38 84.4,60 84.4,55.89 82.39,53.87 79.98,53.87 77.73,51.62 77.73,46.47 79.11,45.09 79.11,36.3 78.08,35.27 73.75,35.27 71.23,32.76 71.23,31.16 71.31,31.09 C106.1
N144770640: length 39.6
  TOP w0.203: J2.B58 104.88,60.02 104.88,57.08 105.71,56.24 107.18,56.24 109.91,53.51 109.91,48.83 107.94,46.86 106.66,46.86 104.65,44.85 104.65,36.91 107.25,34.3 109.87,34.3 111.62,32.55 111.62,31.19 C115.1
N144770880: length 39.6
  TOP w0.203: J2.B59 105.33,59.93 105.33,57.27 105.9,56.7 107.37,56.7 110.37,53.7 110.37,48.64 108.13,46.41 106.85,46.41 105.1,44.66 105.1,37.1 107.44,34.76 110.06,34.76 112.08,32.74 112.08,31.19 C116.1
N144771181: length 28.1
  BOTTOM w0.203: C137.2 70.68,46.36 70.78,46.46 70.78,49.29 72.32,50.84 83.84,50.84 87.11,54.11 87.11,56.01 85.96,57.16 85.96,59.94 J2.A39
N144771420: length 40
  TOP w0.203: J2.B42 88.37,59.97 88.37,54.09 85.87,51.58 83.26,51.58 80.22,48.55 80.22,35.87 78.4,34.04 74.04,34.04 72.56,32.56 72.56,31.14 72.61,31.09 C108.1
N144771900: length 39.8
  TOP w0.203: C102.1 68.59,31.19 68.59,33.51 73.41,38.33 73.41,43.25 71.08,45.58 68.29,45.58 67.19,46.69 67.19,50.61 68.47,51.89 70.68,51.89 74.39,55.6 74.39,59.98 J2.B28
N144772140: length 39.5
  TOP w0.203: C125.1 118.21,31.17 118.21,32.27 119.36,33.42 126.52,33.42 128.84,35.74 128.84,50.49 124.92,54.42 124.92,59.98 J2.B78
N144772500: length 40
  TOP w0.203: C120.1 114.72,31.19 114.72,33.09 118.66,37.03 122.27,37.03 124.31,39.06 124.31,45.25 113.31,56.24 113.31,59.91 J2.B67
N144772741: length 28.3
  BOTTOM w0.203: C149.2 112.94,46.45 112.94,50.56 112.2,51.3 104.73,51.3 103.83,52.2 103.83,53.46 104.66,54.29 110.11,54.29 110.9,55.07 110.9,60 J2.A64
N144773341: length 28.4
  BOTTOM w0.203: C141.2 73.42,46.45 73.42,47.09 74.71,48.38 84.6,48.38 93.97,57.75 93.97,59.93 J2.A47
N144773581: length 28.1
  BOTTOM w0.203: J2.A29 75.94,59.96 75.94,57.8 75.23,57.09 75.23,55.85 75.89,55.18 79.22,55.18 79.57,54.84 79.57,53.5 79.2,53.13 70.17,53.13 68.14,51.1 68.14,46.45 C133.2
N144774000: length 40
  TOP w0.203: J2.B75 121.36,59.95 121.36,55.94 127.59,49.71 127.59,35.97 125.85,34.24 119.27,34.24 117.36,32.32 117.36,31.19 C124.1
N144774240: length 40.1
  TOP w0.203: C117.1 112.94,31.19 112.94,32.67 110.1,35.51 107.48,35.51 105.7,37.3 105.7,43.65 107.34,45.29 110.3,45.29 112.75,47.74 112.75,52.81 108.86,56.7 108.86,60.04 J2.B62
N144774480: length 39.8
  TOP w0.203: J2.B20 66.31,59.9 66.31,54.9 57.06,45.65 57.06,36.91 58.88,35.09 63.84,35.09 65.95,32.98 65.95,31.19 C98.1
N144775140: length 39.6
  TOP w0.203: J2.B46 92.37,59.96 92.37,55.53 81.33,44.5 81.33,35.21 78.9,32.78 74.51,32.78 73.88,32.15 73.88,31.19 C110.1
N144775501: length 28.2
  BOTTOM w0.203: J2.A77 123.6,60.25 123.36,60 123.36,57.3 124.33,56.32 126.72,56.32 129.02,54.02 129.02,50.17 127.61,48.75 118.26,48.75 117.35,47.85 117.35,46.46 C156.2
N144776160: length 39.7
  TOP w0.203: J2.B55 101.39,59.99 101.39,56.15 102.5,55.04 105.99,55.04 107.27,53.76 107.27,49.32 103.9,45.95 103.9,36.52 106.74,33.67 109.58,33.67 110.76,32.5 110.76,31.19 C114.1
N144776640: length 40
  TOP w0.203: J2.B24 70.4,59.99 70.4,56.65 59.14,45.4 59.14,37.37 60.05,36.47 64.59,36.47 67.27,33.79 67.27,31.19 C100.1
N144776880: length 39.7
  TOP w0.203: J2.B19 65.7,60.25 65.85,60.09 65.85,55.09 56.6,45.84 56.6,36.73 58.69,34.64 63.65,34.64 65.49,32.79 65.49,31.19 C97.1
N144777181: length 28.3
  BOTTOM w0.203: J2.A68 114.65,60.23 114.91,59.97 114.91,54.55 115.78,53.68 122.08,53.68 122.63,53.13 122.63,52.13 122.05,51.55 115.41,51.55 114.27,50.41 114.27,46.46 C151.2
N144777421: length 28.3
  BOTTOM w0.203: C150.2 113.4,46.45 113.4,50.75 112.39,51.76 104.92,51.76 104.28,52.39 104.28,53.27 104.85,53.83 110.3,53.83 111.35,54.88 111.35,59.95 J2.A65
N144777781: length 27.9
  BOTTOM w0.203: C144.2 109.45,46.43 109.45,47.55 108.82,48.18 97.32,48.18 95.83,49.67 95.83,53.57 99.37,57.12 99.37,59.97 J2.A53
N144778201: length 28.4
  BOTTOM w0.203: J2.A57 103.38,59.98 103.38,57.3 102.6,56.52 100.31,56.52 98.09,54.3 98.09,51.4 100.16,49.33 109.67,49.33 110.76,48.24 110.76,46.49 110.86,46.38 C146.2
N144778500: length 40
  TOP w0.203: J2.B71 117.39,59.99 117.39,55.91 125.88,47.41 125.88,37.37 124.27,35.76 119,35.76 116.04,32.79 116.04,31.19 C122.1
N144778741: length 28.5
  BOTTOM w0.203: J2.A61 107.38,59.98 107.38,56.38 106.17,55.17 102.23,55.17 100.87,53.8 100.87,51.92 102.32,50.47 110.51,50.47 112.08,48.9 112.08,46.45 C148.2
N144778981: length 28
  BOTTOM w0.203: J2.A44 90.37,59.97 90.37,55.15 84.41,49.19 73.16,49.19 72.56,48.58 72.56,46.45 C140.2
N144779220: length 39.9
  TOP w0.203: J2.B33 79.87,60.03 79.87,57.13 73.78,51.04 73.78,45.32 74.99,44.11 76.28,44.11 77.42,42.97 77.42,37.32 77.02,36.93 72.8,36.93 69.46,33.58 69.46,31.19 C103.1
N144779460: length 39.8
  TOP w0.203: C101.1 68.14,31.19 68.14,33.7 72.96,38.52 72.96,43.06 70.89,45.13 68.1,45.13 66.73,46.5 66.73,50.8 68.28,52.35 70.49,52.35 73.93,55.79 73.93,59.97 J2.B27
N144780060: length 40
  TOP w0.203: C121.1 115.58,31.19 115.58,32.98 118.81,36.21 124.08,36.21 125.43,37.56 125.43,47.22 116.93,55.72 116.93,59.97 J2.B70
N144780361: length 28
  BOTTOM w0.203: C139.2 72.1,46.45 72.1,48.77 72.97,49.64 84.22,49.64 89.91,55.33 89.91,59.98 J2.A43
N144780601: length 28
  BOTTOM w0.203: J2.A40 86.41,60.01 86.41,57.35 87.57,56.19 87.57,53.93 84.03,50.38 72.51,50.38 71.24,49.1 71.24,46.45 C138.2
N144788221: length 27.9
  BOTTOM w0.203: J2.A80 126.9,59.99 126.9,57.63 127.74,56.79 129.19,56.79 130.77,55.2 130.77,49.37 129.45,48.04 118.88,48.04 118.22,47.39 118.22,46.45 C157.2
N144788821: length 28.4
  BOTTOM w0.203: J2.A56 102.93,59.97 102.93,57.49 102.41,56.97 100.12,56.97 97.63,54.49 97.63,51.21 99.97,48.87 109.48,48.87 110.3,48.05 110.3,46.45 C145.2
N144789240: length 39.5
  TOP w0.203: C111.1 108.98,31.19 108.98,31.81 108.57,32.22 106.12,32.22 102.32,36.01 102.32,46.83 104.2,48.71 104.2,52.24 103.51,52.93 99.68,52.93 96.91,55.7 96.91,59.99 J2.B50
N144789780: length 39.9
  TOP w0.203: J2.B41 87.91,59.98 87.91,54.28 85.68,52.04 83.07,52.04 79.77,48.74 79.77,36.06 78.21,34.5 73.85,34.5 72.1,32.75 72.1,31.24 72,31.14 C107.1
N144790260: length 40.1
  TOP w0.203: C118.1 113.4,31.19 113.4,32.86 110.29,35.97 107.67,35.97 106.16,37.49 106.16,43.46 107.53,44.83 110.49,44.83 113.2,47.55 113.2,53 109.35,56.86 109.35,59.94 J2.B63
N144790620: length 39.9
  TOP w0.203: J2.B34 80.33,59.92 80.33,56.94 74.24,50.85 74.24,45.51 75.18,44.57 76.47,44.57 77.87,43.16 77.87,37.13 77.21,36.47 72.99,36.47 69.91,33.39 69.91,31.19 C104.1
N144791101: length 28.5
  BOTTOM w0.203: J2.A21 67.95,59.95 67.95,57.15 66.74,55.93 63.42,55.93 62.16,54.68 62.16,52.17 61.53,51.54 58.72,51.54 58.09,50.91 58.09,49.51 58.75,48.85 65.05,48.85 65.49,48.4 65.49,46.45 C129.2
N144791880: length 39.5
  TOP w0.203: C126.1 118.67,31.2 118.67,32.08 119.55,32.97 126.71,32.97 129.3,35.55 129.3,50.68 125.37,54.61 125.37,59.97 J2.B79
N144792241: length 27.9
  BOTTOM w0.203: J2.A16 62.95,59.94 62.95,57.61 59.99,54.65 56.22,54.65 54.78,53.2 54.78,49.03 56.3,47.51 63.68,47.51 64.17,47.02 64.17,46.45 C127.2
N144792841: length 28.2
  BOTTOM w0.203: C135.2 69.36,46.36 69.45,46.45 69.45,50.14 71.31,52 83.15,52 84.34,53.19 84.34,55.07 81.92,57.49 81.92,59.97 J2.A35
N144793080: length 39.9
  TOP w0.203: J2.B66 112.85,60.04 112.85,56.05 123.85,45.06 123.85,39.25 122.08,37.49 118.47,37.49 114.26,33.28 114.26,31.19 C119.1
N144793501: length 27.9
  BOTTOM w0.203: J2.A17 63.41,60.01 63.41,57.42 60.18,54.19 56.41,54.19 55.23,53.01 55.23,49.21 56.49,47.96 63.87,47.96 64.63,47.21 64.63,46.45 C128.2
N144794040: length 39.7
  TOP w0.203: C113.1 110.3,31.19 110.3,32.31 109.39,33.22 106.55,33.22 103.44,36.33 103.44,46.13 106.81,49.51 106.81,53.57 105.8,54.58 102.31,54.58 100.93,55.96 100.93,59.97 J2.B54
N144794401: length 28.1
  BOTTOM w0.203: C131.2 66.82,46.45 66.82,49.85 66.36,50.3 64.23,50.3 63.39,51.14 63.39,53.93 64.01,54.56 73.5,54.56 73.84,54.9 73.84,55.8 73.57,56.06 72.33,56.06 71.92,56.48 71.92,59.93 71.71,60.14 71.71,60.19 J2.A25
N144794701: length 28.1
  BOTTOM w0.203: J2.A30 76.4,60 76.4,57.61 75.69,56.9 75.69,56.04 76.08,55.64 79.41,55.64 80.03,55.03 80.03,53.31 79.39,52.67 70.36,52.67 68.59,50.91 68.59,46.45 C134.2
N144795060: length 39.7
  TOP w0.203: J2.B15 61.36,59.96 61.36,56.88 54.7,50.21 54.7,36.27 57.26,33.71 63.27,33.71 64.63,32.34 64.63,31.19 C96.1
